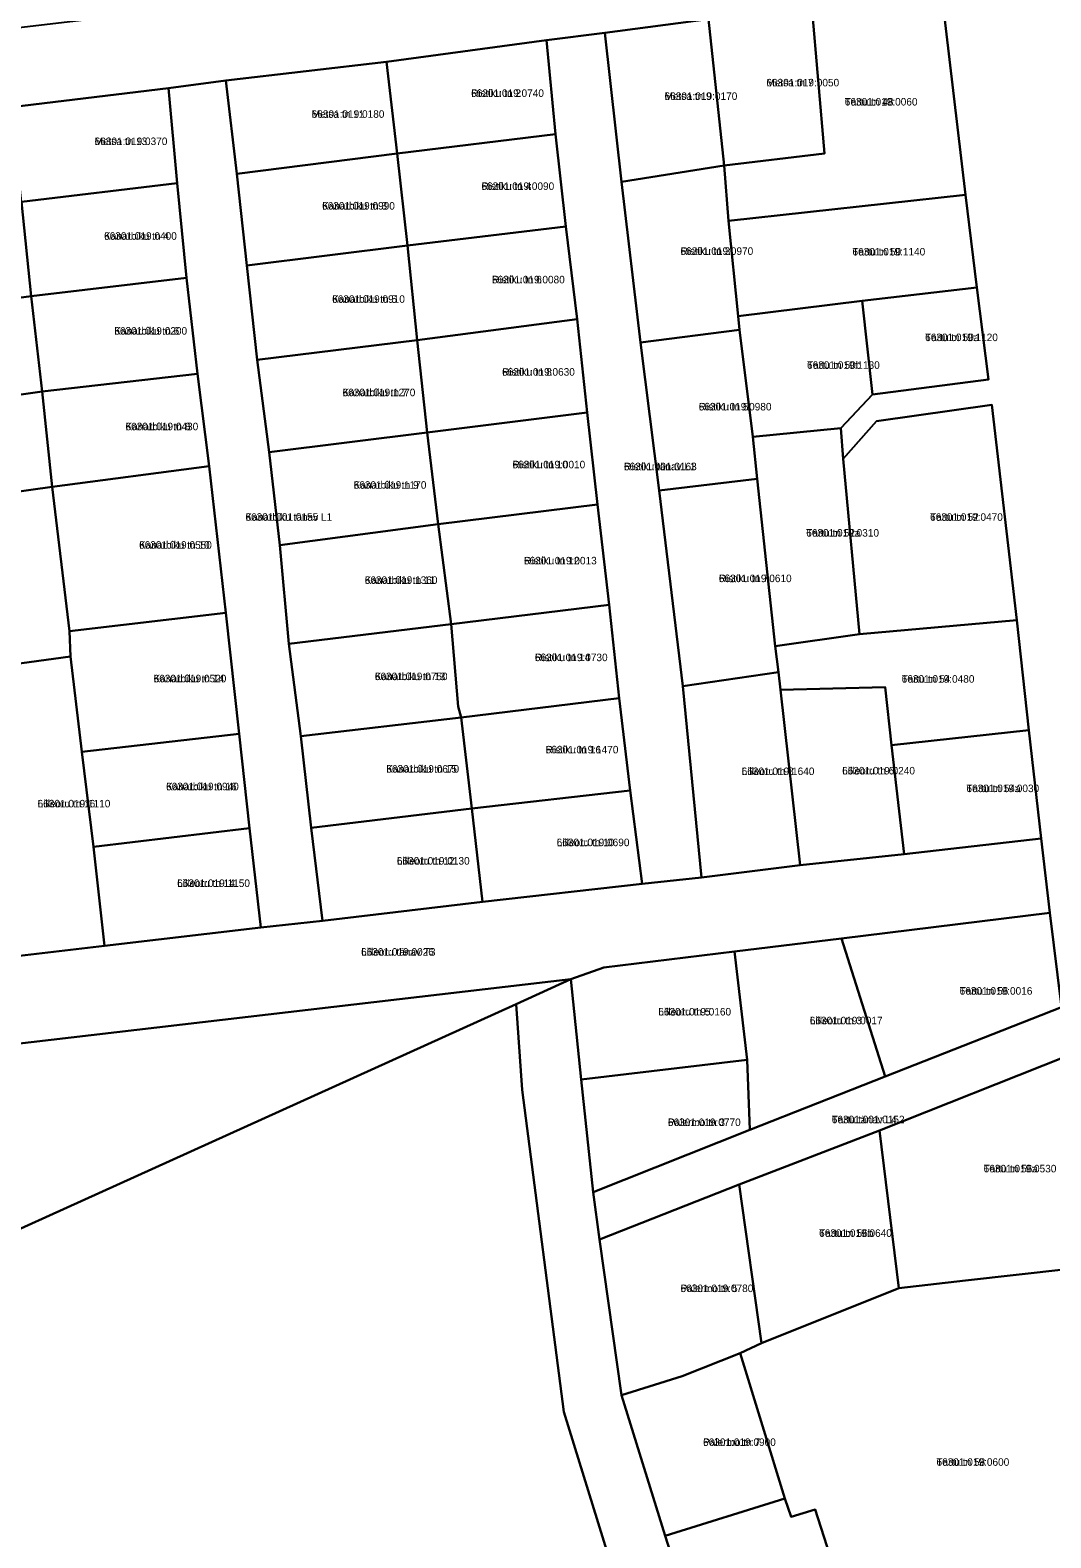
# Model space of a CAD drawing. Extents: x 632278 to 636344, y 6578401 to 6583362.
# Drawn here: x 634323.6 to 634526.9, y 6578915.6 to 6579215.9 of the extents above; entities that cross this region are included whole.
import ezdxf

# ---------------------------------------------------------------- set-up
doc = ezdxf.new("R2010")
doc.units = 0
for name, color, linetype in [('L_AADRESS', 7, 'Continuous'), ('PIIR', 7, 'Continuous'), ('TUNNUS', 7, 'Continuous')]:
    doc.layers.add(name, color=color, linetype=linetype)

msp = doc.modelspace()

# ---------------------------------------------------------------- linework, layer by layer
at = {"layer": 'PIIR'}
for points in [[(634278.15, 6579211.22), (634321.33, 6579216.45), (634346.19, 6579219.38), (634371.24, 6579222.48), (634395.93, 6579225.64), (634407.74, 6579227.15), (634432.23, 6579230.01), (634455.69, 6579232.75), (634503.27, 6579238.27), (634505.1, 6579223.6), (634479.32, 6579220.54), (634458.68, 6579218.14), (634438.08, 6579215.39), (634426.4, 6579213.93), (634394.54, 6579209.62), (634362.56, 6579205.91), (634351.12, 6579204.36), (634319.85, 6579200.59), (634279.04, 6579195.68)], [(634461.81, 6579188.97), (634481.8, 6579191.32), (634479.32, 6579220.54), (634505.1, 6579223.6), (634509.88, 6579183.14), (634462.69, 6579177.91)], [(634479.32, 6579220.54), (634481.8, 6579191.32), (634461.81, 6579188.97), (634458.68, 6579218.14)], [(634438.08, 6579215.39), (634458.68, 6579218.14), (634461.81, 6579188.97), (634441.36, 6579185.69)], [(634426.4, 6579213.93), (634438.08, 6579215.39), (634441.35, 6579185.69), (634445.13, 6579153.71), (634448.91, 6579124.18), (634453.62, 6579085.23), (634457.32, 6579047.13), (634445.46, 6579045.84), (634443.13, 6579064.44), (634440.94, 6579082.83), (634438.9, 6579101.4), (634436.62, 6579121.4), (634434.53, 6579139.75), (634432.53, 6579158.37), (634430.28, 6579176.8), (634428.2, 6579195.19)], [(634394.54, 6579209.62), (634426.4, 6579213.93), (634428.21, 6579195.2), (634396.67, 6579191.32)], [(634394.54, 6579209.62), (634396.67, 6579191.32), (634364.75, 6579187.31), (634362.56, 6579205.91)], [(634351.12, 6579204.36), (634362.56, 6579205.91), (634364.75, 6579187.31), (634366.76, 6579169.02), (634368.79, 6579150.21), (634371.21, 6579131.84), (634373.29, 6579113.34), (634375.12, 6579093.69), (634377.48, 6579075.26), (634379.56, 6579056.98), (634381.78, 6579038.5), (634369.54, 6579037.13), (634367.28, 6579056.97), (634365.22, 6579075.73), (634362.54, 6579099.82), (634359.2, 6579129.04), (634356.92, 6579147.47), (634354.69, 6579166.61), (634352.86, 6579185.43)], [(634352.86, 6579185.43), (634321.82, 6579181.7), (634319.86, 6579200.6), (634351.12, 6579204.36)], [(634396.67, 6579191.32), (634428.21, 6579195.2), (634430.28, 6579176.81), (634398.71, 6579172.99)], [(634364.75, 6579187.31), (634396.67, 6579191.32), (634398.71, 6579172.99), (634366.76, 6579169.02)], [(634441.36, 6579185.69), (634461.81, 6579188.97), (634462.69, 6579177.91), (634464.64, 6579158.91), (634464.88, 6579156.21), (634445.13, 6579153.71)], [(634321.82, 6579181.7), (634352.86, 6579185.43), (634354.69, 6579166.61), (634323.76, 6579162.9)], [(634279.85, 6579176.66), (634321.82, 6579181.7), (634323.76, 6579162.9), (634280.69, 6579157.16)], [(634462.69, 6579177.91), (634509.88, 6579183.14), (634512.19, 6579164.63), (634489.34, 6579161.97), (634464.64, 6579158.91)], [(634432.53, 6579158.37), (634400.65, 6579154.15), (634398.71, 6579172.99), (634430.28, 6579176.81)], [(634366.76, 6579169.02), (634398.71, 6579172.99), (634400.65, 6579154.15), (634368.79, 6579150.21)], [(634356.92, 6579147.47), (634325.98, 6579143.91), (634323.76, 6579162.9), (634354.69, 6579166.61)], [(634491.36, 6579143.31), (634489.34, 6579161.97), (634512.19, 6579164.63), (634514.46, 6579146.31)], [(634280.69, 6579157.16), (634323.76, 6579162.9), (634325.98, 6579143.91), (634281.52, 6579137.63)], [(634464.88, 6579156.21), (634464.64, 6579158.91), (634489.34, 6579161.97), (634491.36, 6579143.31), (634485.07, 6579136.63), (634467.53, 6579134.92)], [(634400.65, 6579154.15), (634432.53, 6579158.37), (634434.53, 6579139.75), (634402.65, 6579135.78)], [(634368.79, 6579150.21), (634400.65, 6579154.15), (634402.65, 6579135.78), (634371.21, 6579131.84)], [(634445.13, 6579153.71), (634464.88, 6579156.21), (634467.53, 6579134.92), (634468.38, 6579126.56), (634448.91, 6579124.18)], [(634325.98, 6579143.91), (634356.92, 6579147.47), (634359.2, 6579129.04), (634327.97, 6579124.96)], [(634282.51, 6579117.79), (634281.52, 6579137.63), (634325.98, 6579143.91), (634327.97, 6579124.96), (634304.76, 6579121.69)], [(634434.53, 6579139.75), (634436.62, 6579121.4), (634404.83, 6579117.52), (634402.65, 6579135.78)], [(634485.52, 6579130.52), (634492.19, 6579138.02), (634515.17, 6579141.25), (634520.17, 6579098.37), (634488.82, 6579095.57)], [(634472.02, 6579093.22), (634468.38, 6579126.56), (634467.53, 6579134.92), (634485.07, 6579136.63), (634485.52, 6579130.52), (634488.82, 6579095.57)], [(634371.21, 6579131.84), (634402.65, 6579135.78), (634404.83, 6579117.52), (634373.29, 6579113.34)], [(634327.97, 6579124.96), (634359.2, 6579129.04), (634362.54, 6579099.82), (634331.41, 6579096.17)], [(634284.12, 6579084.28), (634283.86, 6579092.23), (634307.39, 6579095.67), (634304.76, 6579121.69), (634327.97, 6579124.96), (634331.41, 6579096.17), (634331.6, 6579091.15), (634311.68, 6579088.4)], [(634448.91, 6579124.18), (634468.38, 6579126.56), (634472.02, 6579093.22), (634472.63, 6579088), (634453.62, 6579085.23)], [(634404.83, 6579117.52), (634436.62, 6579121.4), (634438.91, 6579101.41), (634407.47, 6579097.59)], [(634373.29, 6579113.34), (634404.83, 6579117.52), (634407.47, 6579097.59), (634375.12, 6579093.69)], [(634408.83, 6579081.16), (634407.47, 6579097.59), (634438.91, 6579101.41), (634440.94, 6579082.83), (634409.45, 6579079.02)], [(634331.6, 6579091.15), (634331.41, 6579096.17), (634362.54, 6579099.82), (634365.22, 6579075.73), (634333.87, 6579072.17)], [(634375.12, 6579093.69), (634407.47, 6579097.59), (634408.83, 6579081.16), (634409.45, 6579079.02), (634377.48, 6579075.26)], [(634493.88, 6579085.06), (634473.02, 6579084.5), (634472.63, 6579088), (634472.02, 6579093.22), (634488.82, 6579095.57), (634520.17, 6579098.37), (634522.53, 6579076.48), (634495.18, 6579073.47)], [(634314.65, 6579059.76), (634311.68, 6579088.4), (634331.6, 6579091.15), (634333.87, 6579072.17), (634336.19, 6579053.25), (634338.4, 6579033.49), (634318.03, 6579031.1)], [(634453.62, 6579085.23), (634472.63, 6579088), (634473.02, 6579084.5), (634477, 6579049.54), (634457.32, 6579047.13)], [(634495.18, 6579073.47), (634497.66, 6579051.77), (634477, 6579049.54), (634473.02, 6579084.5), (634493.88, 6579085.06)], [(634409.45, 6579079.02), (634440.94, 6579082.83), (634443.13, 6579064.44), (634411.55, 6579060.86)], [(634377.48, 6579075.26), (634409.45, 6579079.02), (634411.55, 6579060.86), (634379.56, 6579056.98)], [(634495.18, 6579073.47), (634522.53, 6579076.48), (634525, 6579054.86), (634497.66, 6579051.77)], [(634333.87, 6579072.17), (634365.22, 6579075.73), (634367.28, 6579056.97), (634336.19, 6579053.25)], [(634411.55, 6579060.86), (634443.13, 6579064.44), (634445.46, 6579045.84), (634413.65, 6579042.25)], [(634379.56, 6579056.98), (634411.55, 6579060.86), (634413.65, 6579042.25), (634381.78, 6579038.5)], [(634270.38, 6579026.57), (634292.2, 6579028.09), (634318.03, 6579031.1), (634338.4, 6579033.49), (634369.54, 6579037.13), (634381.78, 6579038.5), (634413.65, 6579042.25), (634445.46, 6579045.84), (634457.32, 6579047.13), (634477, 6579049.54), (634497.66, 6579051.77), (634525, 6579054.86), (634526.73, 6579040.08), (634485.21, 6579034.95), (634463.87, 6579032.34), (634437.83, 6579029.18), (634431.3, 6579026.85), (634271.37, 6579008.21)], [(634336.19, 6579053.25), (634367.28, 6579056.97), (634369.54, 6579037.13), (634338.4, 6579033.49)], [(634485.21, 6579034.95), (634526.73, 6579040.08), (634529.03, 6579021.28), (634493.92, 6579007.47)], [(634463.87, 6579032.34), (634485.21, 6579034.95), (634493.92, 6579007.47), (634466.96, 6578996.86), (634466.43, 6579010.79)], [(634431.3, 6579026.85), (634437.83, 6579029.18), (634463.87, 6579032.34), (634466.43, 6579010.79), (634433.32, 6579006.89)], [(633930.89, 6578806.81), (633948.27, 6578833.97), (633946.18, 6578841.52), (633974.78, 6578857.65), (634069.59, 6578919.75), (634167.75, 6578962.78), (634235.82, 6578992.62), (634271.37, 6579008.21), (634431.3, 6579026.85), (634420.39, 6579021.86), (634229.37, 6578935.43), (634060.69, 6578873.52), (634046.47, 6578868.29), (633931.37, 6578800.24)], [(634229.37, 6578935.43), (634420.39, 6579021.86), (634421.57, 6579004.79), (634429.87, 6578940.65), (634438.73, 6578912.12), (634461.97, 6578842.78), (634472.68, 6578811.37), (634482.68, 6578786.14), (634525.07, 6578707.28), (634536.28, 6578711.67), (634548.46, 6578682.65), (634490.04, 6578665.45), (634439.52, 6578650.69), (634247.15, 6578594.51)], [(634435.73, 6578984.41), (634466.96, 6578996.86), (634493.92, 6579007.47), (634529.03, 6579021.28), (634529.91, 6579011.46), (634492.76, 6578996.74), (634464.84, 6578985.97), (634437.02, 6578975.01)], [(634433.32, 6579006.89), (634466.43, 6579010.79), (634466.96, 6578996.86), (634435.73, 6578984.41)], [(634492.76, 6578996.74), (634529.91, 6579011.46), (634535.03, 6578975.98), (634530.1, 6578969.11), (634509.9, 6578966.8), (634496.64, 6578965.27)], [(634464.84, 6578985.97), (634492.76, 6578996.74), (634496.64, 6578965.27), (634469.26, 6578954.36)], [(634437.02, 6578975.01), (634464.84, 6578985.97), (634469.26, 6578954.36), (634465.01, 6578952.32), (634453.44, 6578947.77), (634441.36, 6578943.96)], [(634488.67, 6578894.11), (634479.96, 6578921.23), (634475.15, 6578919.72), (634473.89, 6578923.39), (634465.01, 6578952.32), (634469.26, 6578954.36), (634496.64, 6578965.27), (634509.9, 6578966.8), (634530.1, 6578969.11), (634535.03, 6578975.98), (634543.25, 6578913.24), (634536.98, 6578905.9), (634490.39, 6578888.57)], [(634441.36, 6578943.96), (634453.44, 6578947.77), (634465.01, 6578952.32), (634473.89, 6578923.39), (634450.09, 6578915.99)], [(634450.09, 6578915.99), (634473.89, 6578923.39), (634475.15, 6578919.72), (634479.96, 6578921.23), (634488.67, 6578894.11), (634490.39, 6578888.57), (634471.88, 6578881.88), (634459.78, 6578885.69)]]:
    msp.add_lwpolyline(points, close=True, dxfattribs=at)
for points in [[(634543.25, 6578913.24), (634535.03, 6578975.98), (634529.91, 6579011.46), (634529.03, 6579021.28), (634526.73, 6579040.08), (634525, 6579054.86), (634522.53, 6579076.48), (634520.17, 6579098.37), (634515.17, 6579141.25), (634492.19, 6579138.02), (634485.52, 6579130.52), (634485.07, 6579136.63), (634491.36, 6579143.31), (634514.46, 6579146.31), (634512.19, 6579164.63), (634509.88, 6579183.14), (634505.1, 6579223.6)], [(634438.73, 6578912.12), (634429.87, 6578940.65), (634421.57, 6579004.79), (634420.39, 6579021.86), (634431.3, 6579026.85), (634433.32, 6579006.89), (634435.73, 6578984.41), (634437.02, 6578975.01), (634441.36, 6578943.96), (634450.09, 6578915.99), (634459.78, 6578885.69)]]:
    msp.add_lwpolyline(points, dxfattribs=at)

# ---------------------------------------------------------------- texts
at = {"layer": 'L_AADRESS'}
for s, p in [('Metsa tn 7', (634470.24, 6579204.72)), ('Ristiku tn 2', (634411.42, 6579202.62)), ('Metsa tn 9', (634449.95, 6579202.02)), ('Tartu tn 48', (634485.85, 6579200.9)), ('Metsa tn 11', (634379.64, 6579198.46)), ('Metsa tn 13', (634336.4, 6579193.03)), ('Ristiku tn 4', (634413.47, 6579184.09)), ('Kanarbiku tn 3', (634381.72, 6579180.17)), ('Kanarbiku tn 4', (634338.28, 6579174.16)), ('Ristiku tn 3', (634453.12, 6579171.15)), ('Tartu tn 50', (634487.39, 6579171.03)), ('Ristiku tn 6', (634415.57, 6579165.48)), ('Kanarbiku tn 5', (634383.72, 6579161.6)), ('Kanarbiku tn 6', (634340.33, 6579155.26)), ('Tartu tn 50a', (634501.86, 6579153.97)), ('Ristiku tn 8', (634417.58, 6579147.08)), ('Tartu tn 50b', (634478.33, 6579148.45)), ('Kanarbiku tn 7', (634385.8, 6579142.99)), ('Ristiku tn 5', (634456.76, 6579140.16)), ('Kanarbiku tn 8', (634342.55, 6579136.21)), ('Ristiku tn 10', (634419.65, 6579128.63)), ('Ristiku tänav L1', (634441.86, 6579128.24)), ('Kanarbiku tn 9', (634388.01, 6579124.56)), ('Kanarbiku tänav L1', (634366.45, 6579118.18)), ('Tartu tn 52', (634502.85, 6579118.17)), ('Tartu tn 52a', (634478.18, 6579115.02)), ('Kanarbiku tn 10', (634345.26, 6579112.61)), ('Ristiku tn 12', (634421.94, 6579109.49)), ('Kanarbiku tn 11', (634390.21, 6579105.61)), ('Ristiku tn 7', (634460.77, 6579105.95)), ('Ristiku tn 14', (634424.11, 6579090.21)), ('Kanarbiku tn 13', (634392.22, 6579086.43)), ('Kanarbiku tn 14', (634348.15, 6579086)), ('Tartu tn 54', (634497.19, 6579085.92)), ('Ristiku tn 16', (634426.26, 6579071.84)), ('Kanarbiku tn 15', (634394.52, 6579068)), ('Lilleoru tn 8', (634465.31, 6579067.52)), ('Lilleoru tn 6', (634485.34, 6579067.64)), ('Kanarbiku tn 16', (634350.63, 6579064.49)), ('Tartu tn 54a', (634510.09, 6579064.12)), ('Lilleoru tn 16', (634325.04, 6579061.08)), ('Lilleoru tn 10', (634428.46, 6579053.35)), ('Lilleoru tn 12', (634396.62, 6579049.68)), ('Lilleoru tn 14', (634352.85, 6579045.23)), ('Lilleoru tänav T3', (634389.49, 6579031.54)), ('Tartu tn 56', (634508.74, 6579023.77)), ('Lilleoru tn 5', (634448.71, 6579019.62)), ('Lilleoru tn 3', (634478.89, 6579017.87)), ('Palermo tn 3', (634450.62, 6578997.6)), ('Tartu tänav L4', (634483.27, 6578998.15)), ('Tartu tn 56a', (634513.52, 6578988.37)), ('Tartu tn 56b', (634480.74, 6578975.52)), ('Palermo tn 5', (634453.14, 6578964.52)), ('Palermo tn 7', (634457.62, 6578933.87)), ('Tartu tn 58', (634504.13, 6578929.91))]:
    msp.add_text(s, height=1.5, dxfattribs=at).set_placement(p)
at = {"layer": 'TUNNUS'}
for s, p in [('66301:019:0050', (634470.24, 6579204.72)), ('66301:019:0740', (634411.42, 6579202.62)), ('66301:019:0170', (634449.95, 6579202.02)), ('66301:019:0060', (634485.85, 6579200.9)), ('66301:019:0180', (634379.64, 6579198.46)), ('66301:019:0370', (634336.4, 6579193.03)), ('66301:019:0090', (634413.47, 6579184.09)), ('66301:019:0990', (634381.72, 6579180.17)), ('66301:019:0400', (634338.28, 6579174.16)), ('66301:019:0970', (634453.12, 6579171.15)), ('66301:019:1140', (634487.39, 6579171.03)), ('66301:019:0080', (634415.57, 6579165.48)), ('66301:019:0910', (634383.72, 6579161.6)), ('66301:019:0200', (634340.33, 6579155.26)), ('66301:019:1120', (634501.86, 6579153.97)), ('66301:019:0630', (634417.58, 6579147.08)), ('66301:019:1130', (634478.33, 6579148.45)), ('66301:019:1270', (634385.8, 6579142.99)), ('66301:019:0980', (634456.76, 6579140.16)), ('66301:019:0430', (634342.55, 6579136.21)), ('66301:019:0010', (634419.65, 6579128.63)), ('66301:001:0163', (634441.86, 6579128.24)), ('66301:019:1170', (634388.01, 6579124.56)), ('66301:001:0155', (634366.45, 6579118.18)), ('66301:019:0470', (634502.85, 6579118.17)), ('66301:019:0310', (634478.18, 6579115.02)), ('66301:019:0550', (634345.26, 6579112.61)), ('66301:019:0013', (634421.94, 6579109.49)), ('66301:019:1360', (634390.21, 6579105.61)), ('66301:019:0610', (634460.77, 6579105.95)), ('66301:019:0730', (634424.11, 6579090.21)), ('66301:019:0750', (634392.22, 6579086.43)), ('66301:019:0520', (634348.15, 6579086)), ('66301:019:0480', (634497.19, 6579085.92)), ('66301:019:1470', (634426.26, 6579071.84)), ('66301:019:0670', (634394.52, 6579068)), ('66301:019:1640', (634465.31, 6579067.52)), ('66301:019:0240', (634485.34, 6579067.64)), ('66301:019:0940', (634350.63, 6579064.49)), ('66301:019:0030', (634510.09, 6579064.12)), ('66301:019:1110', (634325.04, 6579061.08)), ('66301:019:0690', (634428.46, 6579053.35)), ('66301:019:0130', (634396.62, 6579049.68)), ('66301:019:1150', (634352.85, 6579045.23)), ('66301:019:0026', (634389.49, 6579031.54)), ('66301:019:0016', (634508.74, 6579023.77)), ('66301:019:0160', (634448.71, 6579019.62)), ('66301:019:0017', (634478.89, 6579017.87)), ('66301:019:0770', (634450.62, 6578997.6)), ('66301:001:0152', (634483.27, 6578998.15)), ('66301:019:0530', (634513.52, 6578988.37)), ('66301:019:0640', (634480.74, 6578975.52)), ('66301:019:0780', (634453.14, 6578964.52)), ('66301:019:0900', (634457.62, 6578933.87)), ('66301:019:0600', (634504.13, 6578929.91))]:
    msp.add_text(s, height=1.5, dxfattribs=at).set_placement(p)

doc.saveas('drawing.dxf')
